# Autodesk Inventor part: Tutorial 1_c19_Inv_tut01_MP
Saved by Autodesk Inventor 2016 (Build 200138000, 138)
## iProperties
Created: 2015-04
Part Number: Tutorial 1_c19_Inv_tut01_MP
Material: Generic
Document SubType Name: Modeling
Designer: Sandeep
Density: 1 g/cm^3
Appearance: Default
Author: Sandeep
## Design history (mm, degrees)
derived "c19_Inv_tut01.ipt"
node "Tutorial 1_c19_Inv_tut01_WP"
patch "Boundary Patch5" dims "d15" = 5, "d16" = 0
patch "Boundary Patch6" dims "d17" = 5, "d18" = 0
patch "Boundary Patch7" dims "d19" = 5, "d20" = 0
patch "Boundary Patch8" dims "d21" = 5, "d22" = 0
workplane "Work Plane1"
workplane "Work Plane2"
sketch "Sketch2"
  geometry: L1 (418.75, -500.767)-(418.75, 339.233); L2 (418.75, 339.233)-(-518.75, 339.233); L3 (-518.75, 339.233)-(-518.75, -500.767); L4 (-518.75, -500.767)-(418.75, -500.767); L5 (148.205, -187.466)-(88.248, -152.849) reference; L6 (38.248, -239.452)-(98.205, -274.068) reference; L7 (-198.205, -274.068)-(-138.248, -239.452) reference; L8 (-188.248, -152.849)-(-248.205, -187.466) reference; L9 (-100, 69.233)-(-100, 0) reference; L10 (0, 0)-(0, 69.233) reference; A1 r 140 centre (-50, -130.767) between (88.248, -152.849) and (0, 0) reference; A2 r 50 centre (123.205, -230.767) between (98.205, -274.068) and (148.205, -187.466) reference; A3 r 140 centre (-50, -130.767) between (-138.248, -239.452) and (38.248, -239.452) reference; A4 r 50 centre (-223.205, -230.767) between (-248.205, -187.466) and (-198.205, -274.068) reference; A5 r 140 centre (-50, -130.767) between (-100, 0) and (-188.248, -152.849) reference; A6 r 50 centre (-50, 69.233) between (0, 69.233) and (-100, 69.233) reference; 1 further point
  constraints: 8 end point
  dimensions: "d31" = 468.75 horizontal distance of point (-50, -80.767) L1.end (= 1.5 x Xmax); "d32" = 420 vertical distance of point (-50, -80.767) L1.end (= 1.5 x Ymax); "d33" = 468.75 horizontal distance of point (-50, -80.767) L2.end (= -1.5 x Xmin); "d34" = 420 vertical distance of point (-50, -80.767) L2.end (= 1.5 x Ymax); "d35" = 468.75 horizontal distance of point (-50, -80.767) L3.end (= -1.5 x Xmin); "d36" = 420 vertical distance of point (-50, -80.767) L3.end (= -1.5 x Ymin); "d37" = 468.75 horizontal distance of point (-50, -80.767) L1.start (= 1.5 x Xmax); "d38" = 420 vertical distance of point (-50, -80.767) L1.start (= -1.5 x Ymin)
patch "Boundary Patch10" sketch "Sketch2"
feature "Solid1::c19_Inv_tut01.ipt"
tag "TaggingFeature1"
feature "Solid1::Tutorial 1_c19_Inv_tut01_WP"
tag "TaggingFeature2"
body "Srf5"
body "Srf6"
body "Srf7"
body "Srf8"
body "Srf10"
body "Solid1"
feature "c19_Inv_tut01.ipt_Bodies"
body "Solid2"
feature "Tutorial 1_c19_Inv_tut01_WP_Bodies"
other parameters: "d0" = -157.5, "d1" = 312.5, "d2" = 312.5, "d5" = 315, "d6" = 0, "Xmin" = -312.5, "Zmin" = -157.5, "Xmax" = 312.5, "Zmax" = 157.5
